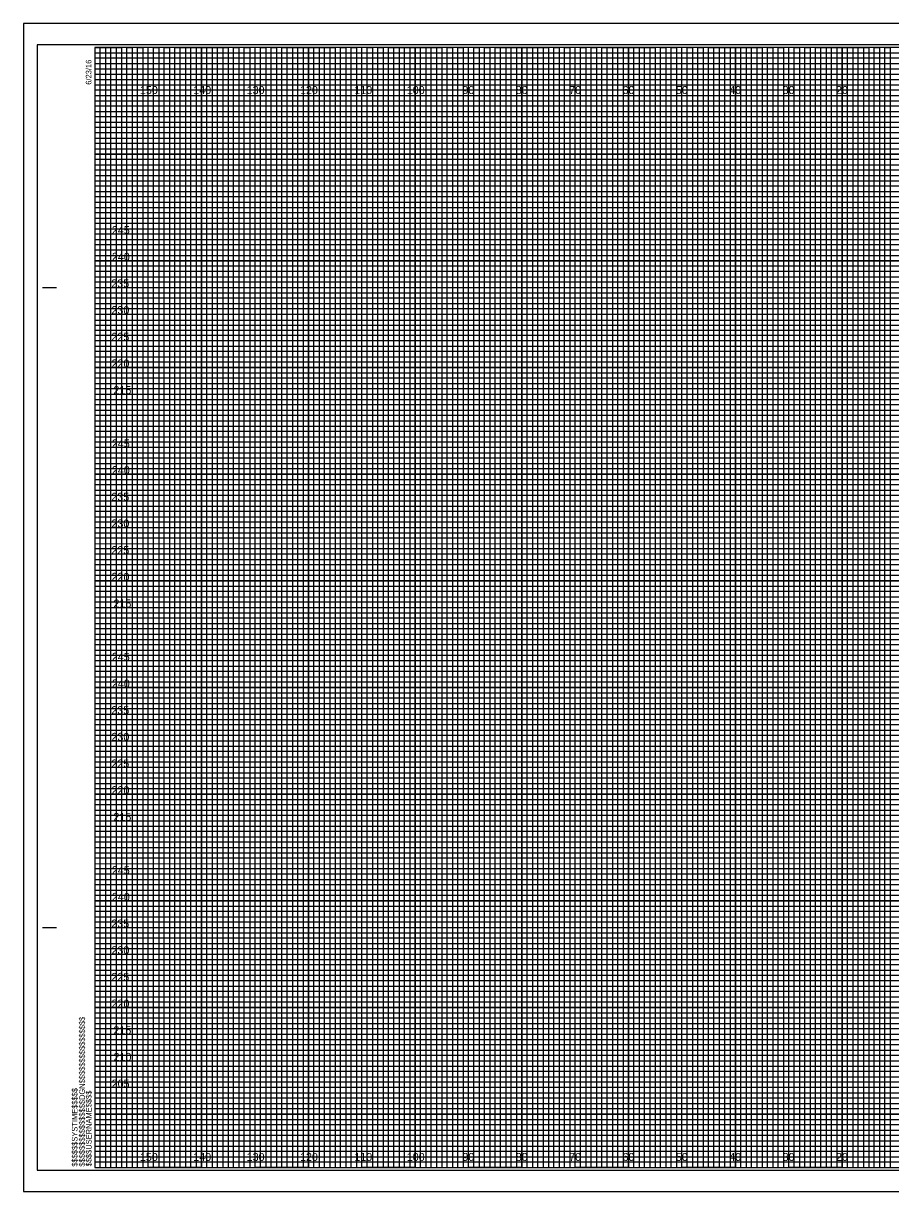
# Model space of a CAD drawing. Extents: x -13 to 323, y -5 to 654.
# Drawn here: x -13.4 to 149.1, y 215.5 to 434.5 of the extents above; entities that cross this region are included whole.
import ezdxf

# ---------------------------------------------------------------- set-up
doc = ezdxf.new("R2010")
doc.units = 0
for name, color, linetype in [('Exist Cross Section Cell', 7, 'Continuous'), ('Exist XS Center Line Elevation Label', 7, 'Continuous'), ('Exist XS Ground Line', 7, 'Continuous'), ('Prop CMT Conc Surface', 7, 'Continuous'), ('Prop CMT Concrete Structures', 7, 'Continuous'), ('Prop CMT DNC', 7, 'Continuous'), ('Prop CMT Pvmt Course 1 Wedge', 7, 'Continuous'), ('Prop CMT Pvmt Course 2', 7, 'Continuous'), ('Prop CMT Pvmt Course 2 Wedge', 7, 'Continuous'), ('Prop CMT Pvmt Course 3', 7, 'Continuous'), ('Prop CMT Subgrade Earthwork', 7, 'Continuous')]:
    doc.layers.add(name, color=color, linetype=linetype)

msp = doc.modelspace()

# ---------------------------------------------------------------- linework, layer by layer
at = {"layer": 'Exist XS Center Line Elevation Label'}
for points in [[(0, 430), (5, 430), (5, 220), (15, 220), (15, 430), (25, 430), (25, 220), (35, 220), (35, 430), (45, 430), (45, 220), (55, 220), (55, 430), (65, 430), (65, 220), (75, 220), (75, 430), (85, 430), (85, 220), (95, 220), (95, 430), (105, 430), (105, 220), (115, 220), (115, 430), (125, 430), (125, 220), (135, 220), (135, 430), (145, 430), (145, 220), (155, 220)], [(0, 425), (275, 425)], [(0, 405), (320, 405), (320, 415), (0, 415)], [(0, 385), (320, 385), (320, 395), (0, 395)], [(0, 365), (320, 365), (320, 375), (0, 375)], [(0, 345), (320, 345), (320, 355), (0, 355)], [(0, 325), (320, 325), (320, 335), (0, 335)], [(0, 305), (320, 305), (320, 315), (0, 315)], [(0, 285), (320, 285), (320, 295), (0, 295)], [(0, 265), (320, 265), (320, 275), (0, 275)], [(0, 245), (320, 245), (320, 255), (0, 255)], [(0, 225), (320, 225), (320, 235), (0, 235)]]:
    msp.add_lwpolyline(points, dxfattribs=at)
at = {"layer": 'Exist XS Ground Line'}
for p, q in [((10, 430), (0, 430)), ((10, 220), (10, 430)), ((30, 430), (20, 430)), ((20, 430), (20, 220)), ((30, 220), (30, 430)), ((50, 430), (40, 430)), ((40, 430), (40, 220)), ((50, 220), (50, 430)), ((70, 430), (60, 430)), ((60, 430), (60, 220)), ((70, 220), (70, 430)), ((90, 430), (80, 430)), ((80, 430), (80, 220)), ((90, 220), (90, 430)), ((110, 430), (100, 430)), ((100, 430), (100, 220)), ((110, 220), (110, 430)), ((130, 430), (120, 430)), ((120, 430), (120, 220)), ((130, 220), (130, 430)), ((150, 430), (140, 430)), ((140, 430), (140, 220)), ((20, 220), (10, 220)), ((40, 220), (30, 220)), ((60, 220), (50, 220)), ((80, 220), (70, 220)), ((100, 220), (90, 220)), ((120, 220), (110, 220)), ((140, 220), (130, 220))]:
    msp.add_line(p, q, dxfattribs=at)
for points in [[(0, 420), (320, 420), (320, 410), (0, 410)], [(0, 400), (320, 400), (320, 390), (0, 390)], [(0, 380), (320, 380), (320, 370), (0, 370)], [(0, 360), (320, 360), (320, 350), (0, 350)], [(0, 340), (320, 340), (320, 330), (0, 330)], [(0, 320), (320, 320), (320, 310), (0, 310)], [(0, 300), (320, 300), (320, 290), (0, 290)], [(0, 280), (320, 280), (320, 270), (0, 270)], [(0, 260), (320, 260), (320, 250), (0, 250)], [(0, 240), (320, 240), (320, 230), (0, 230)]]:
    msp.add_lwpolyline(points, dxfattribs=at)
at = {"layer": 'Prop CMT Conc Surface'}
msp.add_lwpolyline([(-13.4, 215.5), (323.3, 215.5), (323.3, 434.5), (-13.4, 434.5)], close=True, dxfattribs=at)
at = {"layer": 'Prop CMT Concrete Structures'}
for p, q in [((-9.8, 385), (-7.3, 385)), ((-9.7, 385), (-7.2, 385)), ((-9.8, 265), (-7.3, 265)), ((-9.7, 265), (-7.2, 265)), ((0, 220), (0, 220)), ((0, 220), (0, 220)), ((0, 220), (0, 220)), ((0, 220), (0, 220)), ((0, 220), (0, 220)), ((0, 220), (0, 220)), ((0, 220), (0, 220))]:
    msp.add_line(p, q, dxfattribs=at)
msp.add_lwpolyline([(320, 430), (0, 430), (0, 220), (320, 220)], close=True, dxfattribs=at)
at = {"layer": 'Prop CMT DNC'}
for points in [[(0, 220), (1, 220), (1, 430), (2, 430), (2, 220)], [(2, 220), (3, 220), (3, 430), (4, 430), (4, 220)], [(5, 220), (6, 220), (6, 430), (7, 430), (7, 220)], [(7, 220), (8, 220), (8, 430), (9, 430), (9, 220)], [(10, 220), (11, 220), (11, 430), (12, 430), (12, 220)], [(12, 220), (13, 220), (13, 430), (14, 430), (14, 220)], [(15, 220), (16, 220), (16, 430), (17, 430), (17, 220)], [(17, 220), (18, 220), (18, 430), (19, 430), (19, 220)], [(20, 220), (21, 220), (21, 430), (22, 430), (22, 220)], [(22, 220), (23, 220), (23, 430), (24, 430), (24, 220)], [(25, 220), (26, 220), (26, 430), (27, 430), (27, 220)], [(27, 220), (28, 220), (28, 430), (29, 430), (29, 220)], [(30, 220), (31, 220), (31, 430), (32, 430), (32, 220)], [(32, 220), (33, 220), (33, 430), (34, 430), (34, 220)], [(35, 220), (36, 220), (36, 430), (37, 430), (37, 220)], [(37, 220), (38, 220), (38, 430), (39, 430), (39, 220)], [(40, 220), (41, 220), (41, 430), (42, 430), (42, 220)], [(42, 220), (43, 220), (43, 430), (44, 430), (44, 220)], [(45, 220), (46, 220), (46, 430), (47, 430), (47, 220)], [(47, 220), (48, 220), (48, 430), (49, 430), (49, 220)], [(50, 220), (51, 220), (51, 430), (52, 430), (52, 220)], [(52, 220), (53, 220), (53, 430), (54, 430), (54, 220)], [(55, 220), (56, 220), (56, 430), (57, 430), (57, 220)], [(57, 220), (58, 220), (58, 430), (59, 430), (59, 220)], [(60, 220), (61, 220), (61, 430), (62, 430), (62, 220)], [(62, 220), (63, 220), (63, 430), (64, 430), (64, 220)], [(65, 220), (66, 220), (66, 430), (67, 430), (67, 220)], [(67, 220), (68, 220), (68, 430), (69, 430), (69, 220)], [(70, 220), (71, 220), (71, 430), (72, 430), (72, 220)], [(72, 220), (73, 220), (73, 430), (74, 430), (74, 220)], [(75, 220), (76, 220), (76, 430), (77, 430), (77, 220)], [(77, 220), (78, 220), (78, 430), (79, 430), (79, 220)], [(80, 220), (81, 220), (81, 430), (82, 430), (82, 220)], [(82, 220), (83, 220), (83, 430), (84, 430), (84, 220)], [(85, 220), (86, 220), (86, 430), (87, 430), (87, 220)], [(87, 220), (88, 220), (88, 430), (89, 430), (89, 220)], [(90, 220), (91, 220), (91, 430), (92, 430), (92, 220)], [(92, 220), (93, 220), (93, 430), (94, 430), (94, 220)], [(95, 220), (96, 220), (96, 430), (97, 430), (97, 220)], [(97, 220), (98, 220), (98, 430), (99, 430), (99, 220)], [(100, 220), (101, 220), (101, 430), (102, 430), (102, 220)], [(102, 220), (103, 220), (103, 430), (104, 430), (104, 220)], [(105, 220), (106, 220), (106, 430), (107, 430), (107, 220)], [(107, 220), (108, 220), (108, 430), (109, 430), (109, 220)], [(110, 220), (111, 220), (111, 430), (112, 430), (112, 220)], [(112, 220), (113, 220), (113, 430), (114, 430), (114, 220)], [(115, 220), (116, 220), (116, 430), (117, 430), (117, 220)], [(117, 220), (118, 220), (118, 430), (119, 430), (119, 220)], [(120, 220), (121, 220), (121, 430), (122, 430), (122, 220)], [(122, 220), (123, 220), (123, 430), (124, 430), (124, 220)], [(125, 220), (126, 220), (126, 430), (127, 430), (127, 220)], [(127, 220), (128, 220), (128, 430), (129, 430), (129, 220)], [(130, 220), (131, 220), (131, 430), (132, 430), (132, 220)], [(132, 220), (133, 220), (133, 430), (134, 430), (134, 220)], [(135, 220), (136, 220), (136, 430), (137, 430), (137, 220)], [(137, 220), (138, 220), (138, 430), (139, 430), (139, 220)], [(140, 220), (141, 220), (141, 430), (142, 430), (142, 220)], [(142, 220), (143, 220), (143, 430), (144, 430), (144, 220)], [(145, 220), (146, 220), (146, 430), (147, 430), (147, 220)], [(147, 220), (148, 220), (148, 430), (149, 430), (149, 220)]]:
    msp.add_lwpolyline(points, dxfattribs=at)
at = {"layer": 'Prop CMT Pvmt Course 1 Wedge'}
for p, q in [((323.3, 434.5), (-13.4, 434.5)), ((-13.4, 434.5), (-13.4, 215.5)), ((-13.4, 215.5), (323.3, 215.5))]:
    msp.add_line(p, q, dxfattribs=at)
at = {"layer": 'Prop CMT Pvmt Course 2'}
msp.add_lwpolyline([(-10.8, 219.5), (322.4, 219.5), (322.4, 430.5), (-10.8, 430.5)], close=True, dxfattribs=at)
at = {"layer": 'Prop CMT Pvmt Course 3'}
for p, q in [((10, 220), (10, 430)), ((20, 220), (20, 430)), ((30, 220), (30, 430)), ((40, 220), (40, 430)), ((50, 220), (50, 430)), ((60, 220), (60, 430)), ((70, 220), (70, 430)), ((80, 220), (80, 430)), ((90, 220), (90, 430)), ((100, 220), (100, 430)), ((110, 220), (110, 430)), ((120, 220), (120, 430)), ((130, 220), (130, 430)), ((140, 220), (140, 430)), ((0, 420), (320, 420)), ((0, 410), (320, 410)), ((0, 400), (320, 400)), ((0, 390), (320, 390)), ((0, 380), (320, 380)), ((0, 370), (320, 370)), ((0, 360), (320, 360)), ((0, 350), (320, 350)), ((0, 340), (320, 340)), ((0, 330), (320, 330)), ((0, 320), (320, 320)), ((0, 310), (320, 310)), ((0, 300), (320, 300)), ((0, 290), (320, 290)), ((0, 280), (320, 280)), ((0, 270), (320, 270)), ((0, 260), (320, 260)), ((0, 250), (320, 250)), ((0, 240), (320, 240)), ((0, 230), (320, 230))]:
    msp.add_line(p, q, dxfattribs=at)
at = {"layer": 'Prop CMT Subgrade Earthwork'}
for p, q in [((0, 429), (260, 429)), ((260, 427.98), (0, 427.98)), ((0, 427.98), (0, 427)), ((0, 427), (260, 427)), ((260, 425.89), (0, 425.89)), ((0, 425.89), (0, 424)), ((0, 424), (320, 424))]:
    msp.add_line(p, q, dxfattribs=at)
for points in [[(0, 423), (270, 423), (320, 423), (320, 422), (0, 422)], [(0, 421), (320, 421), (320, 419), (0, 419)], [(0, 418), (320, 418), (320, 417), (0, 416.98)], [(0, 416), (320, 416), (320, 414), (0, 414)], [(0, 413), (320, 413), (320, 412), (0, 412)], [(0, 411), (320, 411), (320, 409), (0, 409)], [(0, 408), (320, 408), (320, 407), (0, 407)], [(0, 406), (320, 406), (320, 404), (0, 404)], [(0, 403), (320, 403), (320, 402), (0, 402)], [(0, 401), (320, 401), (320, 399), (0, 399)], [(0, 398), (320, 398), (320, 397), (0, 397)], [(0, 396), (320, 396), (320, 393.95), (320, 393), (320, 392), (0, 392)], [(0, 394), (320, 394), (320, 393), (0, 393)], [(0, 391), (320, 391), (320, 389), (0, 389.03)], [(0, 389.03), (320, 389), (320, 388), (0, 388)], [(0, 387), (320, 387), (320, 386), (0, 386)], [(0, 384), (320, 384), (320, 383), (0, 383)], [(0, 382), (320, 382), (320, 381), (0, 381)], [(-0.07, 378.89), (320, 378.89), (320, 377.88), (-0.07, 377.88)], [(0, 377), (320, 377), (320, 376), (0, 376)], [(0, 374), (320, 374), (320, 373), (0, 373)], [(0, 372), (320, 372), (320, 371), (0, 371)], [(0, 369), (320, 369), (320, 368), (0, 368)], [(0, 367), (320, 367), (320, 366), (0, 366)], [(0, 364), (320, 364), (320, 363), (0, 363)], [(0, 362), (320, 362), (320, 361), (0, 361)], [(0, 359), (320, 359), (319.99, 357.98), (0, 358)], [(0, 357), (320, 357), (320, 356), (0, 356)], [(0, 354), (320, 354), (320, 353), (0, 353)], [(0, 352), (320, 352), (320, 351), (0, 351)], [(0, 349), (320, 349), (320, 348), (0, 348)], [(0, 347), (320, 347), (320, 346), (0, 346)], [(0, 344), (320, 344), (320, 343), (0, 343)], [(0, 342), (320, 342), (320, 341), (0, 341)], [(0, 339), (320, 339), (320, 338), (0, 338)], [(0, 336.99), (320.07, 336.91), (320, 336), (0, 336)], [(0, 334), (320, 334), (320, 333), (0, 333)], [(0, 332), (320, 332), (320, 331), (0, 331)], [(0, 329), (320, 329), (320, 328), (0, 328)], [(0, 327), (320, 327), (320, 326), (0, 326)], [(0, 324), (320, 324), (320, 323), (0, 323)], [(0, 322), (320, 322), (320, 321), (0, 321)], [(0, 319), (320, 319), (320, 318), (0, 318)], [(0, 317), (320, 317), (320, 316), (0, 316)], [(0, 314), (320, 314), (320, 313), (0, 313)], [(0, 312), (320, 312), (320, 311), (0, 311)], [(0, 309), (320, 309), (320, 308), (0, 308)], [(0, 307), (320, 307), (320, 306), (0, 306)], [(0, 304), (320, 304), (320, 303), (0, 303)], [(0, 302), (320, 302), (320, 301), (0, 301)], [(0, 299), (320, 299), (319.99, 297.98), (0, 298)], [(0, 297), (320, 297), (320, 296), (0, 296)], [(0, 294), (320, 294), (320, 293), (0, 293)], [(0, 292), (320, 292), (320, 291), (0, 291)], [(0, 289), (320, 289), (320, 288), (0, 288)], [(0, 287), (320, 287), (320, 286), (0, 286)], [(0, 284), (320, 284), (320, 283), (0, 283)], [(0, 282), (320, 282), (320, 281), (0, 281)], [(0, 279), (320, 279), (320, 278), (0, 278)], [(0, 276.99), (320.07, 276.91), (320, 276), (0, 276)], [(0, 274), (320, 274), (320, 273), (0, 273)], [(0, 272), (320, 272), (320, 271), (0, 271)], [(0, 269), (320, 269), (320, 268), (0, 268)], [(0, 267), (320, 267), (320, 266), (0, 266)], [(0, 264), (320, 264), (320, 263), (0, 263)], [(0, 262), (320, 262), (320, 261), (0, 261)], [(0, 259), (320, 259), (320, 258), (0, 258)], [(0, 257), (320, 257), (320, 256), (0, 256)], [(0, 254), (320, 254), (320, 253), (0, 253)], [(0, 252), (320, 252), (320, 251), (0, 251)], [(0, 249), (320, 249), (320, 248), (0, 248)], [(0, 247), (320, 247), (320, 246), (0, 246)], [(0, 244), (320, 244), (320, 243), (0, 243)], [(0, 242), (320, 242), (320, 241), (0, 241)], [(0, 239), (320, 239), (320, 238), (0, 238)], [(0, 237), (320, 237), (320, 236), (0, 236)], [(0, 234), (320, 234), (320, 233), (0, 233)], [(0, 232), (320, 232), (320, 231), (0, 231)], [(0, 229), (320, 229), (320, 228), (0, 228)], [(0, 227), (320, 227), (320, 226), (0, 226)], [(0, 224), (320, 224), (320, 223), (0, 223)], [(0, 222), (320, 222), (320, 221), (0, 221)]]:
    msp.add_lwpolyline(points, dxfattribs=at)

# ---------------------------------------------------------------- texts
at = {"layer": 'Exist Cross Section Cell'}
for s, p in [('150', (8.44, 421.25)), ('140', (18.44, 421.25)), ('130', (28.44, 421.25)), ('120', (38.44, 421.25)), ('110', (48.62, 421.25)), ('100', (58.44, 421.25)), ('90', (68.86, 421.25)), ('80', (78.86, 421.25)), ('70', (88.86, 421.25)), ('60', (98.86, 421.25)), ('50', (108.86, 421.25)), ('40', (118.86, 421.25)), ('30', (128.86, 421.25)), ('20', (138.86, 421.25)), ('150', (8.44, 221.25)), ('140', (18.44, 221.25)), ('130', (28.44, 221.25)), ('120', (38.44, 221.25)), ('110', (48.62, 221.25)), ('100', (58.44, 221.25)), ('90', (68.86, 221.25)), ('80', (78.86, 221.25)), ('70', (88.86, 221.25)), ('60', (98.86, 221.25)), ('50', (108.86, 221.25)), ('40', (118.86, 221.25)), ('30', (128.86, 221.25)), ('20', (138.86, 221.25))]:
    msp.add_text(s, height=1.5, dxfattribs=at).set_placement(p)
at = {"layer": 'Prop CMT Concrete Structures'}
for s, p in [('6/23/16', (-0.65, 423)), ('$$$$$$$$$$$$$$$$DGN$$$$$$$$$$$$$$$$', (-1.88, 220.18)), ('$$$$$$SYSTIME$$$$$', (-3.26, 220.18)), ('$$$$USERNAME$$$$', (-0.62, 220.23))]:
    msp.add_text(s, height=1.05, rotation=90, dxfattribs=at).set_placement(p)
at = {"layer": 'Prop CMT Pvmt Course 2 Wedge'}
for s, p in [('245', (3.18, 395)), ('240', (3.19, 390)), ('235', (3.09, 385)), ('230', (3.11, 380)), ('225', (3.1, 375)), ('220', (3.12, 370)), ('215', (3.48, 365)), ('245', (3.18, 355)), ('240', (3.19, 350)), ('235', (3.09, 345)), ('230', (3.11, 340)), ('225', (3.1, 335)), ('220', (3.12, 330)), ('215', (3.48, 325)), ('245', (3.18, 315)), ('240', (3.19, 310)), ('235', (3.09, 305)), ('230', (3.11, 300)), ('225', (3.1, 295)), ('220', (3.12, 290)), ('215', (3.48, 285)), ('245', (3.18, 275)), ('240', (3.19, 270)), ('235', (3.09, 265)), ('230', (3.11, 260)), ('225', (3.1, 255)), ('220', (3.12, 250)), ('215', (3.48, 245)), ('210', (3.5, 240)), ('205', (3.15, 235))]:
    msp.add_text(s, height=1.5, dxfattribs=at).set_placement(p)

doc.saveas('drawing.dxf')
